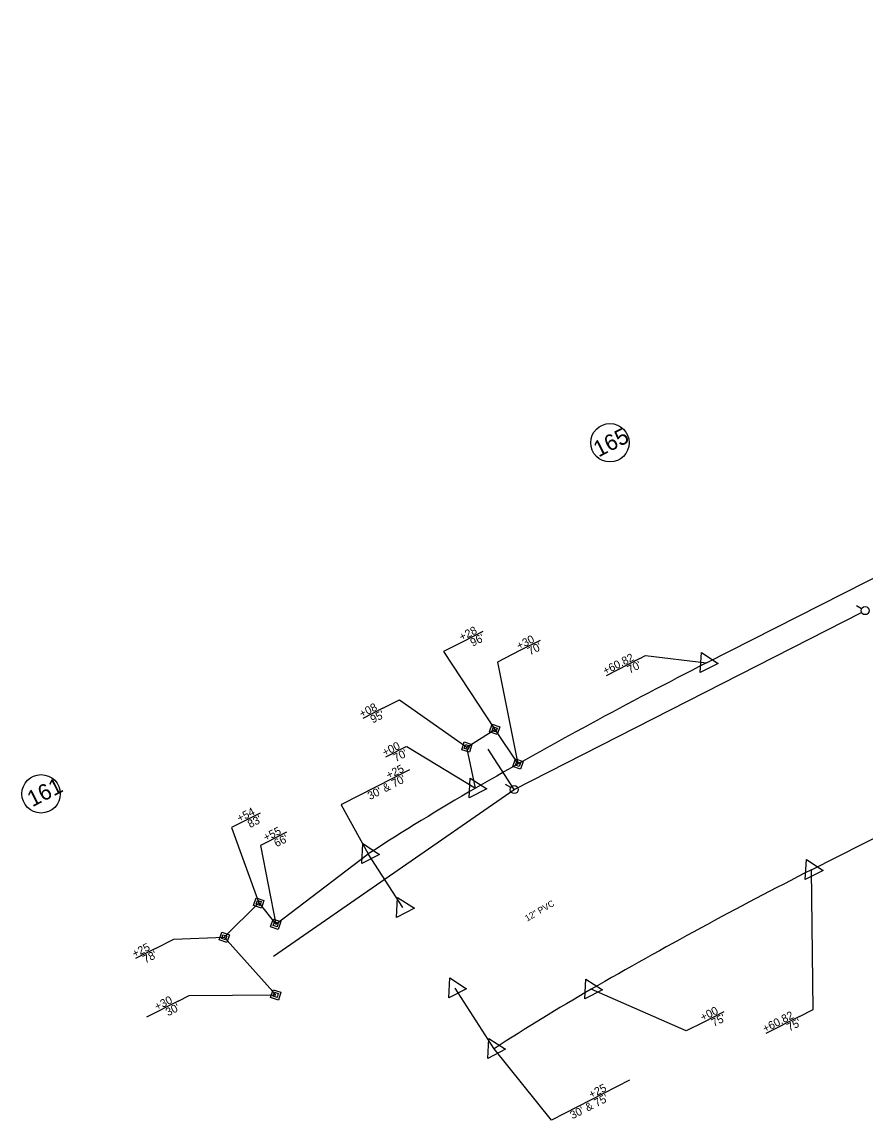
# Model space of a CAD drawing. Extents: x 2320946 to 2332748, y 597838 to 612698.
# Drawn here: x 2331193 to 2331720, y 611820 to 612507 of the extents above; entities that cross this region are included whole.
import ezdxf

# ---------------------------------------------------------------- set-up
doc = ezdxf.new("R2010")
doc.units = 0
for name, color, linetype in [('Default', 7, 'Continuous'), ('Prop Easement Permanent Utility', 7, 'Continuous'), ('Prop Easement Permanent Utility Station Offsets', 7, 'Continuous'), ('Prop Parcel Number CELL', 7, 'Continuous'), ('Prop ROW Marker CELL', 7, 'Continuous'), ('Prop ROW Permanent Easement CELL', 7, 'Continuous'), ('Prop ROW RW Lines', 7, 'Continuous'), ('Prop ROW Station Offsets', 7, 'Continuous'), ('Scratch_Level_1', 7, 'Continuous')]:
    doc.layers.add(name, color=color, linetype=linetype)

msp = doc.modelspace()

# ---------------------------------------------------------------- linework, layer by layer
at = {"layer": 'Prop Easement Permanent Utility'}
for p, q in [((2331471.12, 612053.46), (2331488.56, 612064.52)), ((2331488.56, 612064.52), (2331503.12, 612042.89)), ((2331476.46, 612027.69), (2331471.12, 612053.46)), ((2331351.59, 611942.73), (2331409.39, 611986.68)), ((2331319.42, 611934.58), (2331340.98, 611956.05)), ((2331340.98, 611956.05), (2331351.59, 611942.73)), ((2331351.6, 611898.6), (2331319.42, 611934.58))]:
    msp.add_line(p, q, dxfattribs=at)
at = {"layer": 'Prop Easement Permanent Utility Station Offsets'}
for p, q in [((2331481.1, 612125.66), (2331468.55, 612119.28)), ((2331516.98, 612120.17), (2331504.35, 612113.75)), ((2331418.6, 612077.7), (2331406.05, 612071.32)), ((2331341.82, 612012.25), (2331329.26, 612005.86)), ((2331358.37, 612000.26), (2331345.89, 611993.91)), ((2331276.33, 611927.64), (2331263.85, 611921.3)), ((2331290.53, 611894.67), (2331270.82, 611884.65))]:
    msp.add_line(p, q, dxfattribs=at)
for points in [[(2331468.55, 612119.28), (2331456.58, 612113.19), (2331488.56, 612064.52)], [(2331504.35, 612113.75), (2331490.22, 612106.57), (2331503.12, 612042.89)], [(2331418.6, 612077.7), (2331428.91, 612082.94), (2331471.12, 612053.46)], [(2331329.26, 612005.86), (2331324, 612003.19), (2331340.98, 611956.05)], [(2331345.89, 611993.91), (2331342.06, 611991.97), (2331351.59, 611942.73)], [(2331276.33, 611927.64), (2331287.77, 611933.45), (2331319.42, 611934.58)], [(2331290.53, 611894.67), (2331297.37, 611898.15), (2331351.6, 611898.6)]]:
    msp.add_lwpolyline(points, dxfattribs=at)
at = {"layer": 'Prop Parcel Number CELL'}
for p, q in [((2331560.62, 612243.64), (2331560.62, 612243.64)), ((2331204.85, 612024.24), (2331204.85, 612024.24))]:
    msp.add_line(p, q, dxfattribs=at)
for centre in [(2331560.62, 612243.64), (2331204.85, 612024.24)]:
    msp.add_circle(centre, 12, dxfattribs=at)
at = {"layer": 'Prop ROW Marker CELL'}
for p, q in [((2331621.07, 612106.06), (2331621.07, 612106.06)), ((2331488.56, 612064.52), (2331488.56, 612064.52)), ((2331471.12, 612053.46), (2331471.12, 612053.46)), ((2331503.12, 612042.89), (2331503.12, 612042.89)), ((2331476.46, 612027.69), (2331476.46, 612027.69)), ((2331409.39, 611986.68), (2331409.39, 611986.68)), ((2331686.78, 611976.8), (2331686.78, 611976.8)), ((2331340.98, 611956.05), (2331340.98, 611956.05)), ((2331431.1, 611953.09), (2331431.1, 611953.09)), ((2331351.59, 611942.73), (2331351.59, 611942.73)), ((2331319.42, 611934.58), (2331319.42, 611934.58)), ((2331463.72, 611902.73), (2331463.72, 611902.73)), ((2331548.87, 611902.07), (2331548.87, 611902.07)), ((2331351.6, 611898.6), (2331351.6, 611898.6)), ((2331488.18, 611864.96), (2331488.18, 611864.96))]:
    msp.add_line(p, q, dxfattribs=at)
for points in [[(2331617.13, 612100.02), (2331617.81, 612112.48), (2331628.28, 612105.68)], [(2331472.52, 612021.65), (2331473.19, 612034.11), (2331483.66, 612027.31)], [(2331405.45, 611980.64), (2331406.13, 611993.1), (2331416.59, 611986.3)], [(2331682.84, 611970.76), (2331683.52, 611983.22), (2331693.98, 611976.43)], [(2331427.16, 611947.05), (2331427.84, 611959.51), (2331438.31, 611952.71)], [(2331459.78, 611896.69), (2331460.46, 611909.15), (2331470.92, 611902.35)], [(2331544.93, 611896.03), (2331545.61, 611908.49), (2331556.08, 611901.69)], [(2331484.24, 611858.91), (2331484.92, 611871.37), (2331495.38, 611864.58)]]:
    msp.add_lwpolyline(points, close=True, dxfattribs=at)
at = {"layer": 'Prop ROW Permanent Easement CELL'}
for points in [[(2331486.93, 612067.73), (2331491.77, 612066.16), (2331490.19, 612061.32), (2331485.35, 612062.89)], [(2331487.74, 612066.13), (2331490.16, 612065.34), (2331489.37, 612062.92), (2331486.95, 612063.71)], [(2331469.49, 612056.67), (2331474.33, 612055.09), (2331472.75, 612050.25), (2331467.91, 612051.83)], [(2331470.31, 612055.06), (2331472.73, 612054.28), (2331471.94, 612051.86), (2331469.52, 612052.64)], [(2331501.49, 612046.09), (2331506.33, 612044.52), (2331504.75, 612039.68), (2331499.91, 612041.25)], [(2331502.3, 612044.49), (2331504.72, 612043.7), (2331503.93, 612041.28), (2331501.51, 612042.07)], [(2331339.35, 611959.26), (2331344.19, 611957.68), (2331342.61, 611952.84), (2331337.77, 611954.42)], [(2331340.16, 611957.66), (2331342.58, 611956.87), (2331341.79, 611954.45), (2331339.37, 611955.24)], [(2331349.96, 611945.94), (2331354.8, 611944.36), (2331353.22, 611939.52), (2331348.38, 611941.1)], [(2331350.77, 611944.33), (2331353.19, 611943.54), (2331352.4, 611941.12), (2331349.98, 611941.91)], [(2331317.79, 611937.79), (2331322.63, 611936.21), (2331321.05, 611931.37), (2331316.21, 611932.95)], [(2331318.6, 611936.19), (2331321.02, 611935.4), (2331320.23, 611932.98), (2331317.81, 611933.77)], [(2331349.96, 611901.81), (2331354.8, 611900.23), (2331353.23, 611895.39), (2331348.39, 611896.97)], [(2331350.78, 611900.2), (2331353.2, 611899.41), (2331352.41, 611896.99), (2331349.99, 611897.78)]]:
    msp.add_lwpolyline(points, close=True, dxfattribs=at)
at = {"layer": 'Prop ROW RW Lines'}
for p, q in [((2331686.78, 611976.8), (2332729.02, 612506.63)), ((2331621.07, 612106.06), (2331939.47, 612267.92)), ((2331431.13, 611953.11), (2331409.39, 611986.68)), ((2331488.2, 611864.97), (2331463.74, 611902.74))]:
    msp.add_line(p, q, dxfattribs=at)
for centre, radius, start, end in [((2333037.52, 609319.71), 3125.71, 116.94653, 119.96199), ((2332235.58, 610710.83), 1520, 119.96199, 122.92556), ((2333037.52, 609319.71), 2980.71, 116.94653, 119.96199), ((2332235.58, 610710.83), 1375, 119.96199, 122.92556)]:
    msp.add_arc(centre, radius, start, end, dxfattribs=at)
at = {"layer": 'Prop ROW Station Offsets'}
for p, q in [((2331579.27, 612108.77), (2331558.18, 612098.04)), ((2331432.94, 612053.52), (2331420.31, 612047.11)), ((2331435.22, 612039.18), (2331393.19, 612017.81)), ((2331631.93, 611888.04), (2331619.31, 611881.62)), ((2331679.16, 611885.16), (2331658.07, 611874.44)), ((2331572.93, 611845.24), (2331524.02, 611820.38))]:
    msp.add_line(p, q, dxfattribs=at)
for points in [[(2331579.27, 612108.77), (2331582.91, 612110.62), (2331621.07, 612106.06)], [(2331432.94, 612053.52), (2331433.61, 612053.87), (2331476.46, 612027.69)], [(2331393.19, 612017.81), (2331392.48, 612017.45), (2331409.39, 611986.68)], [(2331679.16, 611885.16), (2331687.69, 611889.49), (2331686.78, 611976.8)], [(2331619.31, 611881.62), (2331608.41, 611876.08), (2331548.87, 611902.07)], [(2331524.02, 611820.38), (2331488.2, 611864.97)]]:
    msp.add_lwpolyline(points, dxfattribs=at)
at = {"layer": 'Scratch_Level_1'}
for p, q in [((2331718.09, 612139.96), (2331714.84, 612141.82)), ((2331500.8, 612026.91), (2331484.56, 612052.13)), ((2331350.18, 611922.73), (2331500.8, 612026.91)), ((2331498.63, 612028.15), (2331495.38, 612030.02))]:
    msp.add_line(p, q, dxfattribs=at)
msp.add_lwpolyline([(2331500.8, 612026.91), (2331718.04, 612137.59)], dxfattribs=at)
for centre in [(2331720.26, 612138.72), (2331500.8, 612026.91)]:
    msp.add_circle(centre, 2.5, dxfattribs=at)

# ---------------------------------------------------------------- texts
at = {"layer": 'Default'}
msp.add_text('12" PVC', height=4, rotation=30.6206, dxfattribs=at).set_placement((2331508.92, 611944.32))
at = {"layer": 'Prop Easement Permanent Utility Station Offsets'}
for s, p in [('+28', (2331467.94, 612119.67)), ("96'", (2331474.83, 612116.16)), ('+30', (2331503.81, 612114.18)), ("70'", (2331510.71, 612110.68)), ('+08', (2331405.44, 612071.71)), ("95'", (2331412.33, 612068.21)), ('+54', (2331328.9, 612006.38)), ("83'", (2331335.56, 612002.75)), ('+55', (2331345.38, 611994.35)), ("66'", (2331352.11, 611990.76)), ('+25', (2331263.34, 611921.74)), ("78'", (2331270.07, 611918.15)), ('+30', (2331277.36, 611888.68)), ("30'", (2331284.27, 611885.18))]:
    msp.add_text(s, height=5, rotation=26.94705, dxfattribs=at).set_placement(p)
at = {"layer": 'Prop Parcel Number CELL'}
for s, p in [('165', (2331553.56, 612234.45)), ('161', (2331199.37, 612015.84))]:
    msp.add_text(s, height=10, rotation=26.9454, dxfattribs=at).set_placement(p)
at = {"layer": 'Prop ROW Station Offsets'}
for s, p in [('+60.82', (2331557.77, 612098.54)), ("70'", (2331573, 612099.27)), ('+00', (2331419.77, 612047.53)), ("70'", (2331426.67, 612044.03)), ('+25', (2331422.23, 612033.28)), ("30' & 70'", (2331410.55, 612020.33)), ('+00', (2331618.76, 611882.04)), ("75'", (2331625.67, 611878.54)), ('+60.82', (2331657.67, 611874.93)), ("75'", (2331672.9, 611875.67)), ('+25', (2331548.92, 611833.74)), ("30' & 75'", (2331537.24, 611820.79))]:
    msp.add_text(s, height=5, rotation=26.94705, dxfattribs=at).set_placement(p)

doc.saveas('drawing.dxf')
